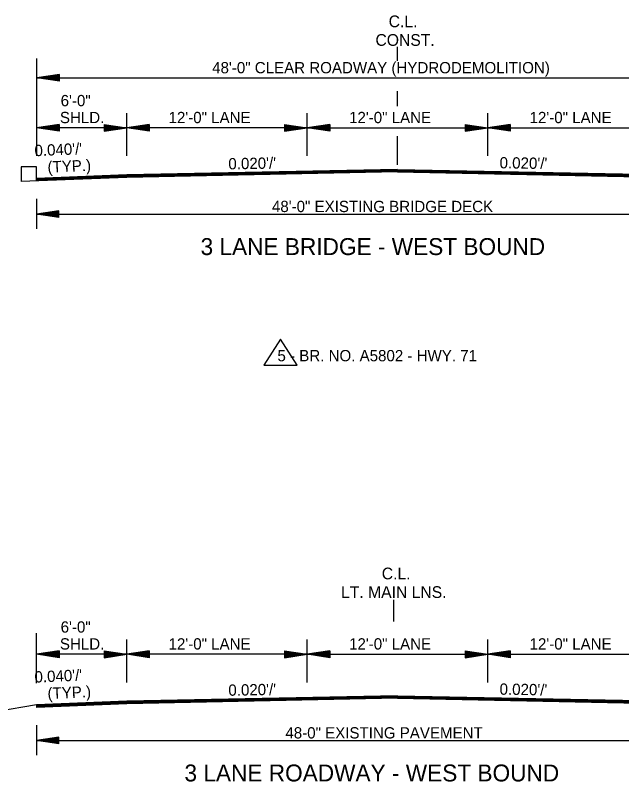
# Model space of a CAD drawing. Extents: x 542112 to 1930787, y -1968972 to 596640.
# Drawn here: x 544301 to 544704, y -1950515 to -1950005 of the extents above; entities that cross this region are included whole.
import ezdxf

# ---------------------------------------------------------------- set-up
doc = ezdxf.new("R2010")
doc.units = 0
doc.layers.add('R_Border', color=7, linetype='Continuous')
doc.layers.add('R_Draft', color=7, linetype='Continuous')

msp = doc.modelspace()

# ---------------------------------------------------------------- linework, layer by layer
at = {"layer": 'R_Border'}
for p, q in [((544314.54, -1950106.13), (544304.37, -1950106.13)), ((544304.37, -1950106.13), (544304.37, -1950115.94)), ((544314.54, -1950115.53), (544314.54, -1950106.13)), ((544476.8, -1950220.64), (544465.76, -1950237.94)), ((544487.84, -1950237.94), (544476.8, -1950220.64)), ((544465.76, -1950237.94), (544487.84, -1950237.94))]:
    msp.add_line(p, q, dxfattribs=at)
at = {"layer": 'R_Draft'}
for p, q in [((544554.54, -1950035.71), (544554.54, -1950026.4)), ((544314.54, -1950034.21), (544314.54, -1950098.92)), ((544329.89, -1950044.72), (544314.89, -1950046.97)), ((544329.89, -1950045.09), (544317.39, -1950046.97)), ((544329.89, -1950049.22), (544329.89, -1950044.72)), ((544314.54, -1950046.97), (544794.54, -1950046.97)), ((544329.89, -1950049.22), (544314.89, -1950046.97)), ((544329.89, -1950048.84), (544317.39, -1950046.97)), ((544329.89, -1950045.47), (544319.97, -1950046.97)), ((544329.89, -1950048.46), (544319.97, -1950046.97)), ((544329.89, -1950045.85), (544322.47, -1950046.97)), ((544329.89, -1950048.08), (544322.47, -1950046.97)), ((544329.89, -1950046.23), (544325.01, -1950046.97)), ((544329.89, -1950047.69), (544325.01, -1950046.97)), ((544329.89, -1950046.61), (544327.52, -1950046.97)), ((544329.89, -1950047.32), (544327.52, -1950046.97)), ((544554.54, -1950065.71), (544554.54, -1950055.84)), ((544374.54, -1950098.92), (544374.54, -1950070.37)), ((544494.54, -1950098.92), (544494.54, -1950070.37)), ((544614.54, -1950098.92), (544614.54, -1950070.37)), ((544329.54, -1950078.01), (544314.54, -1950080.26)), ((544374.54, -1950080.26), (544314.54, -1950080.26)), ((544329.54, -1950082.51), (544314.54, -1950080.26)), ((544329.54, -1950078.39), (544317.05, -1950080.26)), ((544329.54, -1950082.14), (544317.05, -1950080.26)), ((544329.54, -1950078.77), (544319.63, -1950080.26)), ((544329.54, -1950081.75), (544319.63, -1950080.26)), ((544329.54, -1950079.14), (544322.12, -1950080.26)), ((544329.54, -1950081.38), (544322.12, -1950080.26)), ((544329.54, -1950079.53), (544324.67, -1950080.26)), ((544329.54, -1950081), (544324.67, -1950080.26)), ((544329.54, -1950079.91), (544327.17, -1950080.26)), ((544329.54, -1950080.61), (544327.17, -1950080.26)), ((544329.54, -1950078.01), (544329.54, -1950082.51)), ((544359.54, -1950078.01), (544374.54, -1950080.26)), ((544359.54, -1950078.01), (544359.54, -1950082.51)), ((544359.54, -1950078.39), (544372.04, -1950080.26)), ((544359.54, -1950078.77), (544369.46, -1950080.26)), ((544359.54, -1950079.14), (544366.96, -1950080.26)), ((544359.54, -1950079.53), (544364.42, -1950080.26)), ((544359.54, -1950079.91), (544361.91, -1950080.26)), ((544359.54, -1950082.51), (544374.54, -1950080.26)), ((544359.54, -1950081), (544364.42, -1950080.26)), ((544359.54, -1950081.75), (544369.46, -1950080.26)), ((544359.54, -1950082.14), (544372.04, -1950080.26)), ((544359.54, -1950081.38), (544366.96, -1950080.26)), ((544359.54, -1950080.61), (544361.91, -1950080.26)), ((544389.54, -1950078.01), (544374.54, -1950080.26)), ((544494.54, -1950080.26), (544374.54, -1950080.26)), ((544389.54, -1950082.51), (544374.54, -1950080.26)), ((544389.54, -1950078.39), (544377.05, -1950080.26)), ((544389.54, -1950082.14), (544377.05, -1950080.26)), ((544389.54, -1950078.77), (544379.63, -1950080.26)), ((544389.54, -1950081.75), (544379.63, -1950080.26)), ((544389.54, -1950079.14), (544382.12, -1950080.26)), ((544389.54, -1950081.38), (544382.12, -1950080.26)), ((544389.54, -1950079.53), (544384.67, -1950080.26)), ((544389.54, -1950081), (544384.67, -1950080.26)), ((544389.54, -1950079.91), (544387.17, -1950080.26)), ((544389.54, -1950080.61), (544387.17, -1950080.26)), ((544389.54, -1950078.01), (544389.54, -1950082.51)), ((544479.54, -1950078.01), (544494.54, -1950080.26)), ((544479.54, -1950078.01), (544479.54, -1950082.51)), ((544479.54, -1950078.39), (544492.04, -1950080.26)), ((544479.54, -1950078.77), (544489.46, -1950080.26)), ((544479.54, -1950079.14), (544486.96, -1950080.26)), ((544479.54, -1950079.53), (544484.42, -1950080.26)), ((544479.54, -1950079.91), (544481.91, -1950080.26)), ((544479.54, -1950082.51), (544494.54, -1950080.26)), ((544479.54, -1950081), (544484.42, -1950080.26)), ((544479.54, -1950081.75), (544489.46, -1950080.26)), ((544479.54, -1950082.14), (544492.04, -1950080.26)), ((544479.54, -1950081.38), (544486.96, -1950080.26)), ((544479.54, -1950080.61), (544481.91, -1950080.26)), ((544509.54, -1950078.01), (544494.54, -1950080.26)), ((544509.54, -1950082.51), (544494.54, -1950080.26)), ((544494.54, -1950080.26), (544614.54, -1950080.26)), ((544509.54, -1950078.39), (544497.05, -1950080.26)), ((544509.54, -1950082.14), (544497.05, -1950080.26)), ((544509.54, -1950078.77), (544499.63, -1950080.26)), ((544509.54, -1950081.75), (544499.63, -1950080.26)), ((544509.54, -1950079.14), (544502.12, -1950080.26)), ((544509.54, -1950081.38), (544502.12, -1950080.26)), ((544509.54, -1950079.53), (544504.67, -1950080.26)), ((544509.54, -1950081), (544504.67, -1950080.26)), ((544509.54, -1950079.91), (544507.17, -1950080.26)), ((544509.54, -1950080.61), (544507.17, -1950080.26)), ((544509.54, -1950078.01), (544509.54, -1950082.51)), ((544599.54, -1950078.01), (544614.54, -1950080.26)), ((544599.54, -1950078.01), (544599.54, -1950082.51)), ((544599.54, -1950078.39), (544612.04, -1950080.26)), ((544599.54, -1950078.77), (544609.46, -1950080.26)), ((544599.54, -1950079.14), (544606.96, -1950080.26)), ((544599.54, -1950079.53), (544604.42, -1950080.26)), ((544599.54, -1950079.91), (544601.91, -1950080.26)), ((544599.54, -1950082.51), (544614.54, -1950080.26)), ((544599.54, -1950081), (544604.42, -1950080.26)), ((544599.54, -1950081.75), (544609.46, -1950080.26)), ((544599.54, -1950082.14), (544612.04, -1950080.26)), ((544599.54, -1950081.38), (544606.96, -1950080.26)), ((544599.54, -1950080.61), (544601.91, -1950080.26)), ((544629.54, -1950078.01), (544614.54, -1950080.26)), ((544614.54, -1950080.26), (544734.54, -1950080.26)), ((544629.54, -1950082.51), (544614.54, -1950080.26)), ((544629.54, -1950078.39), (544617.05, -1950080.26)), ((544629.54, -1950082.14), (544617.05, -1950080.26)), ((544629.54, -1950078.77), (544619.63, -1950080.26)), ((544629.54, -1950081.75), (544619.63, -1950080.26)), ((544629.54, -1950079.14), (544622.12, -1950080.26)), ((544629.54, -1950081.38), (544622.12, -1950080.26)), ((544629.54, -1950079.53), (544624.67, -1950080.26)), ((544629.54, -1950081), (544624.67, -1950080.26)), ((544629.54, -1950079.91), (544627.17, -1950080.26)), ((544629.54, -1950080.61), (544627.17, -1950080.26)), ((544629.54, -1950078.01), (544629.54, -1950082.51)), ((544554.54, -1950104.72), (544554.54, -1950085.77)), ((544374.54, -1950111.47), (544314.54, -1950113.87)), ((544554.54, -1950107.87), (544374.54, -1950111.47)), ((544554.54, -1950108.17), (544374.54, -1950111.77)), ((544554.54, -1950108.47), (544374.54, -1950112.07)), ((544554.54, -1950108.77), (544374.54, -1950112.37)), ((544554.54, -1950109.07), (544374.54, -1950112.67)), ((544554.54, -1950109.37), (544374.54, -1950112.97)), ((544554.54, -1950109.53), (544374.54, -1950113.13)), ((544554.54, -1950107.87), (544734.54, -1950111.47)), ((544554.54, -1950108.17), (544734.54, -1950111.77)), ((544554.54, -1950108.47), (544734.54, -1950112.07)), ((544554.54, -1950108.77), (544734.54, -1950112.37)), ((544554.54, -1950109.07), (544734.54, -1950112.67)), ((544554.54, -1950109.37), (544734.54, -1950112.97)), ((544554.54, -1950109.53), (544734.54, -1950113.13)), ((544374.61, -1950113.13), (544304.37, -1950115.94)), ((544374.55, -1950111.77), (544314.54, -1950114.17)), ((544374.56, -1950112.07), (544314.54, -1950114.47)), ((544374.57, -1950112.37), (544314.54, -1950114.77)), ((544374.58, -1950112.67), (544314.54, -1950115.07)), ((544374.59, -1950112.97), (544314.54, -1950115.37)), ((544314.54, -1950127.31), (544314.54, -1950147.31)), ((544329.53, -1950135.3), (544314.53, -1950137.55)), ((544329.53, -1950135.68), (544317.03, -1950137.55)), ((544329.53, -1950136.06), (544319.61, -1950137.55)), ((544329.53, -1950136.44), (544322.11, -1950137.55)), ((544329.53, -1950136.82), (544324.65, -1950137.55)), ((544329.53, -1950139.8), (544329.53, -1950135.3)), ((544329.53, -1950139.8), (544314.53, -1950137.55)), ((544314.54, -1950137.55), (544794.54, -1950137.55)), ((544329.53, -1950139.43), (544317.03, -1950137.55)), ((544329.53, -1950139.05), (544319.61, -1950137.55)), ((544329.53, -1950138.67), (544322.11, -1950137.55)), ((544329.53, -1950138.28), (544324.65, -1950137.55)), ((544329.53, -1950137.2), (544327.16, -1950137.55)), ((544329.53, -1950137.91), (544327.16, -1950137.55)), ((544552.23, -1950408.4), (544552.23, -1950394.08)), ((544314.34, -1950416.17), (544314.34, -1950449.48)), ((544374.54, -1950448.92), (544374.54, -1950420.37)), ((544494.54, -1950448.92), (544494.54, -1950420.37)), ((544614.54, -1950448.92), (544614.54, -1950420.37)), ((544329.54, -1950428.01), (544314.54, -1950430.26)), ((544374.54, -1950430.26), (544314.54, -1950430.26)), ((544329.54, -1950432.51), (544314.54, -1950430.26)), ((544329.54, -1950428.39), (544317.05, -1950430.26)), ((544329.54, -1950432.14), (544317.05, -1950430.26)), ((544329.54, -1950428.77), (544319.63, -1950430.26)), ((544329.54, -1950431.75), (544319.63, -1950430.26)), ((544329.54, -1950429.14), (544322.12, -1950430.26)), ((544329.54, -1950431.38), (544322.12, -1950430.26)), ((544329.54, -1950429.53), (544324.67, -1950430.26)), ((544329.54, -1950431), (544324.67, -1950430.26)), ((544329.54, -1950429.91), (544327.17, -1950430.26)), ((544329.54, -1950430.61), (544327.17, -1950430.26)), ((544329.54, -1950428.01), (544329.54, -1950432.51)), ((544359.54, -1950428.01), (544374.54, -1950430.26)), ((544359.54, -1950428.01), (544359.54, -1950432.51)), ((544359.54, -1950428.39), (544372.04, -1950430.26)), ((544359.54, -1950428.77), (544369.46, -1950430.26)), ((544359.54, -1950429.14), (544366.96, -1950430.26)), ((544359.54, -1950429.53), (544364.42, -1950430.26)), ((544359.54, -1950429.91), (544361.91, -1950430.26)), ((544359.54, -1950432.51), (544374.54, -1950430.26)), ((544359.54, -1950431), (544364.42, -1950430.26)), ((544359.54, -1950431.75), (544369.46, -1950430.26)), ((544359.54, -1950432.14), (544372.04, -1950430.26)), ((544359.54, -1950431.38), (544366.96, -1950430.26)), ((544359.54, -1950430.61), (544361.91, -1950430.26)), ((544389.54, -1950428.01), (544374.54, -1950430.26)), ((544494.54, -1950430.26), (544374.54, -1950430.26)), ((544389.54, -1950432.51), (544374.54, -1950430.26)), ((544389.54, -1950428.39), (544377.05, -1950430.26)), ((544389.54, -1950432.14), (544377.05, -1950430.26)), ((544389.54, -1950428.77), (544379.63, -1950430.26)), ((544389.54, -1950431.75), (544379.63, -1950430.26)), ((544389.54, -1950429.14), (544382.12, -1950430.26)), ((544389.54, -1950431.38), (544382.12, -1950430.26)), ((544389.54, -1950429.53), (544384.67, -1950430.26)), ((544389.54, -1950431), (544384.67, -1950430.26)), ((544389.54, -1950429.91), (544387.17, -1950430.26)), ((544389.54, -1950430.61), (544387.17, -1950430.26)), ((544389.54, -1950428.01), (544389.54, -1950432.51)), ((544479.54, -1950428.01), (544494.54, -1950430.26)), ((544479.54, -1950428.01), (544479.54, -1950432.51)), ((544479.54, -1950428.39), (544492.04, -1950430.26)), ((544479.54, -1950428.77), (544489.46, -1950430.26)), ((544479.54, -1950429.14), (544486.96, -1950430.26)), ((544479.54, -1950429.53), (544484.42, -1950430.26)), ((544479.54, -1950429.91), (544481.91, -1950430.26)), ((544479.54, -1950432.51), (544494.54, -1950430.26)), ((544479.54, -1950431), (544484.42, -1950430.26)), ((544479.54, -1950431.75), (544489.46, -1950430.26)), ((544479.54, -1950432.14), (544492.04, -1950430.26)), ((544479.54, -1950431.38), (544486.96, -1950430.26)), ((544479.54, -1950430.61), (544481.91, -1950430.26)), ((544509.54, -1950428.01), (544494.54, -1950430.26)), ((544509.54, -1950432.51), (544494.54, -1950430.26)), ((544494.54, -1950430.26), (544614.54, -1950430.26)), ((544509.54, -1950428.39), (544497.05, -1950430.26)), ((544509.54, -1950432.14), (544497.05, -1950430.26)), ((544509.54, -1950428.77), (544499.63, -1950430.26)), ((544509.54, -1950431.75), (544499.63, -1950430.26)), ((544509.54, -1950429.14), (544502.12, -1950430.26)), ((544509.54, -1950431.38), (544502.12, -1950430.26)), ((544509.54, -1950429.53), (544504.67, -1950430.26)), ((544509.54, -1950431), (544504.67, -1950430.26)), ((544509.54, -1950429.91), (544507.17, -1950430.26)), ((544509.54, -1950430.61), (544507.17, -1950430.26)), ((544509.54, -1950428.01), (544509.54, -1950432.51)), ((544599.54, -1950428.01), (544614.54, -1950430.26)), ((544599.54, -1950428.01), (544599.54, -1950432.51)), ((544599.54, -1950428.39), (544612.04, -1950430.26)), ((544599.54, -1950428.77), (544609.46, -1950430.26)), ((544599.54, -1950429.14), (544606.96, -1950430.26)), ((544599.54, -1950429.53), (544604.42, -1950430.26)), ((544599.54, -1950429.91), (544601.91, -1950430.26)), ((544599.54, -1950432.51), (544614.54, -1950430.26)), ((544599.54, -1950431), (544604.42, -1950430.26)), ((544599.54, -1950431.75), (544609.46, -1950430.26)), ((544599.54, -1950432.14), (544612.04, -1950430.26)), ((544599.54, -1950431.38), (544606.96, -1950430.26)), ((544599.54, -1950430.61), (544601.91, -1950430.26)), ((544629.54, -1950428.01), (544614.54, -1950430.26)), ((544614.54, -1950430.26), (544734.54, -1950430.26)), ((544629.54, -1950432.51), (544614.54, -1950430.26)), ((544629.54, -1950428.39), (544617.05, -1950430.26)), ((544629.54, -1950432.14), (544617.05, -1950430.26)), ((544629.54, -1950428.77), (544619.63, -1950430.26)), ((544629.54, -1950431.75), (544619.63, -1950430.26)), ((544629.54, -1950429.14), (544622.12, -1950430.26)), ((544629.54, -1950431.38), (544622.12, -1950430.26)), ((544629.54, -1950429.53), (544624.67, -1950430.26)), ((544629.54, -1950431), (544624.67, -1950430.26)), ((544629.54, -1950429.91), (544627.17, -1950430.26)), ((544629.54, -1950430.61), (544627.17, -1950430.26)), ((544629.54, -1950428.01), (544629.54, -1950432.51)), ((544554.54, -1950457.87), (544374.54, -1950461.47)), ((544554.54, -1950457.87), (544734.54, -1950461.47)), ((544374.54, -1950461.47), (544314.54, -1950463.87)), ((544374.55, -1950461.77), (544314.54, -1950464.17)), ((544374.56, -1950462.07), (544314.54, -1950464.47)), ((544374.57, -1950462.37), (544314.54, -1950464.77)), ((544374.58, -1950462.67), (544314.54, -1950465.07)), ((544374.59, -1950462.97), (544314.54, -1950465.37)), ((544554.54, -1950458.17), (544374.54, -1950461.77)), ((544554.54, -1950458.47), (544374.54, -1950462.07)), ((544554.54, -1950458.77), (544374.54, -1950462.37)), ((544554.54, -1950459.07), (544374.54, -1950462.67)), ((544554.54, -1950459.37), (544374.54, -1950462.97)), ((544554.54, -1950459.53), (544374.54, -1950463.13)), ((544554.54, -1950458.17), (544734.54, -1950461.77)), ((544554.54, -1950458.47), (544734.54, -1950462.07)), ((544554.54, -1950458.77), (544734.54, -1950462.37)), ((544554.54, -1950459.07), (544734.54, -1950462.67)), ((544554.54, -1950459.37), (544734.54, -1950462.97)), ((544554.54, -1950459.53), (544734.54, -1950463.13)), ((544314.54, -1950463.87), (544210.86, -1950481.15)), ((544374.61, -1950463.13), (544314.54, -1950465.53)), ((544314.54, -1950463.87), (544314.54, -1950465.53)), ((544314.54, -1950477.31), (544314.54, -1950497.31)), ((544329.53, -1950485.3), (544314.53, -1950487.55)), ((544329.53, -1950489.8), (544314.53, -1950487.55)), ((544314.54, -1950487.55), (544794.54, -1950487.55)), ((544329.53, -1950485.68), (544317.03, -1950487.55)), ((544329.53, -1950489.43), (544317.03, -1950487.55)), ((544329.53, -1950486.06), (544319.61, -1950487.55)), ((544329.53, -1950489.05), (544319.61, -1950487.55)), ((544329.53, -1950486.44), (544322.11, -1950487.55)), ((544329.53, -1950488.67), (544322.11, -1950487.55)), ((544329.53, -1950486.82), (544324.65, -1950487.55)), ((544329.53, -1950488.28), (544324.65, -1950487.55)), ((544329.53, -1950487.2), (544327.16, -1950487.55)), ((544329.53, -1950487.91), (544327.16, -1950487.55)), ((544329.53, -1950489.8), (544329.53, -1950485.3))]:
    msp.add_line(p, q, dxfattribs=at)

# ---------------------------------------------------------------- texts
for s, height, p in [('C.L.', 7.8, (544548.7, -1950013.31)), ('CONST.', 7.8, (544539.91, -1950025.68)), ('48\'-0" CLEAR ROADWAY (HYDRODEMOLITION)', 7.5, (544431.35, -1950043.95)), ('6\'-0" ', 7.5, (544330.63, -1950065.84)), ('SHLD.', 7.5, (544330.13, -1950077.09)), ('12\'-0" LANE', 7.5, (544402.36, -1950077.09)), ('12\'-0" LANE', 7.5, (544522.36, -1950077.09)), ('12\'-0" LANE', 7.5, (544642.36, -1950077.09)), ('48\'-0" EXISTING BRIDGE DECK', 7.5, (544471.1, -1950136.23)), ('3 LANE BRIDGE - WEST BOUND', 11.25, (544423.66, -1950164.8)), ('5 - BR. NO. A5802 - HWY. 71', 7.5, (544474.76, -1950235.43)), ('C.L.', 7.8, (544544.12, -1950380.43)), ('LT. MAIN LNS.', 7.8, (544517.04, -1950392.8)), ('6\'-0" ', 7.5, (544330.63, -1950415.84)), ('SHLD.', 7.5, (544330.13, -1950427.09)), ('12\'-0" LANE', 7.5, (544402.36, -1950427.09)), ('12\'-0" LANE', 7.5, (544522.36, -1950427.09)), ('12\'-0" LANE', 7.5, (544642.36, -1950427.09)), ('48-0" EXISTING PAVEMENT', 7.5, (544480.04, -1950486.23)), ('3 LANE ROADWAY - WEST BOUND', 11.25, (544412.94, -1950514.8))]:
    msp.add_text(s, height=height, dxfattribs=at).set_placement(p)
for s, rotation, p in [("  0.040'/'", 2.448, (544307.84, -1950099.34)), (' (TYP.)', 2.448, (544319.26, -1950110.12)), ("0.020'/'", 0.9719, (544442.19, -1950107.85)), ("0.020'/'", 359.0281, (544622.37, -1950107.1)), ("  0.040'/'", 2.448, (544307.84, -1950449.34)), (' (TYP.)', 2.448, (544319.26, -1950460.12)), ("0.020'/'", 0.9719, (544442.19, -1950457.85)), ("0.020'/'", 359.0281, (544622.37, -1950457.1))]:
    msp.add_text(s, height=7.5, rotation=rotation, dxfattribs=at).set_placement(p)

doc.saveas('drawing.dxf')
